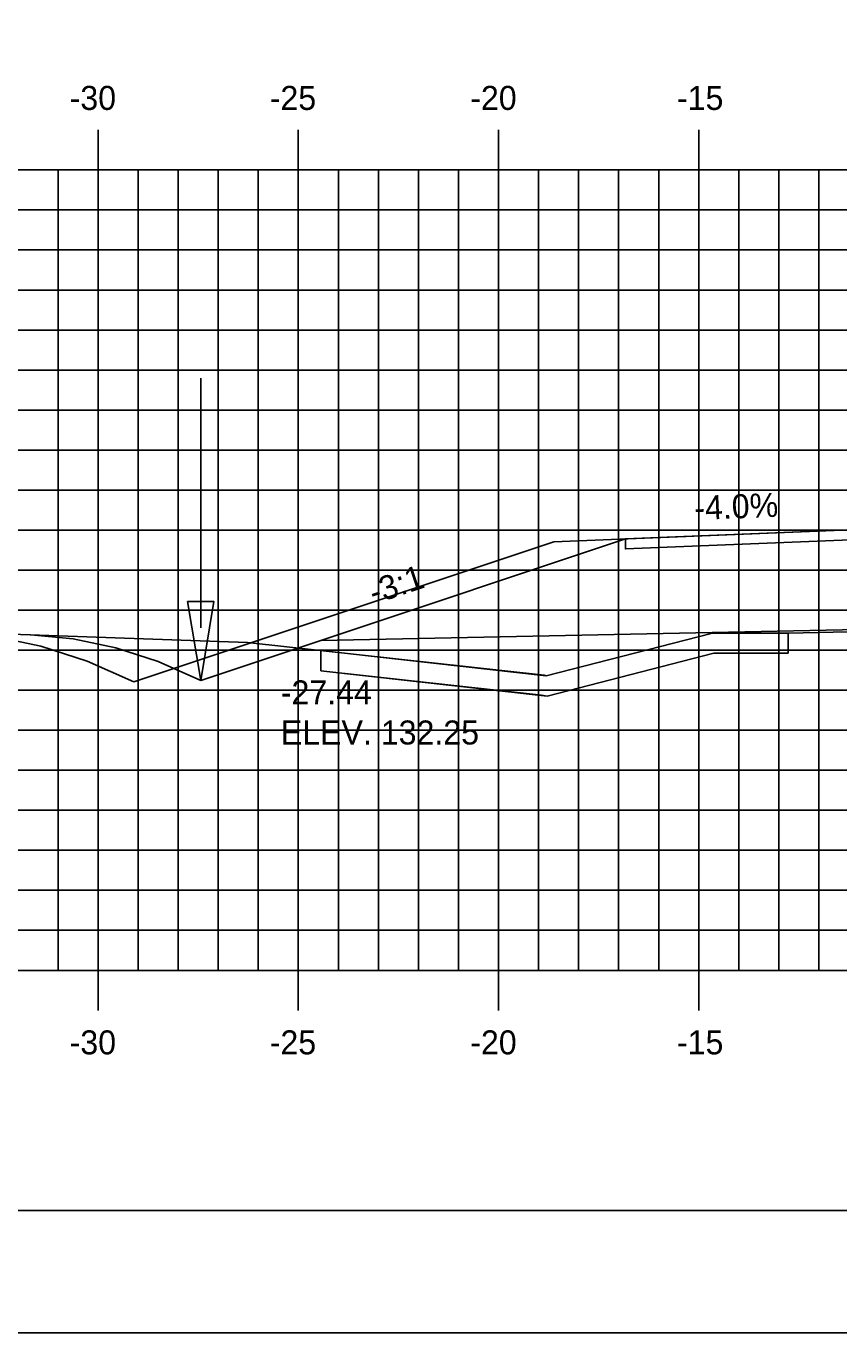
# Model space of a CAD drawing. Extents: x 1146525 to 1146695, y 608981 to 609091.
# Drawn here: x 1146575.87 to 1146596.17, y 608981.28 to 609013.93 of the extents above; entities that cross this region are included whole.
import ezdxf

# ---------------------------------------------------------------- set-up
doc = ezdxf.new("R2010")
doc.units = 0
for name, color, linetype in [('ANNOTATION', 7, 'Continuous'), ('BORDER', 7, 'Continuous'), ('D_Drainage_Ditch_Line', 7, 'Continuous'), ('D_Roadway_Edge_Shoulder', 7, 'Continuous'), ('D_Roadway_SlopeLines', 7, 'Continuous'), ('D_Roadway_SubGrade', 7, 'Continuous'), ('D_Text_Standard', 7, 'Continuous'), ('H_V ANNOTATION', 7, 'Continuous'), ('MAJOR', 7, 'Continuous'), ('MINOR', 7, 'Continuous'), ('PLOT BOUNDARY', 7, 'Continuous'), ('S_Roadway_Centerline', 7, 'Continuous'), ('SHADING', 7, 'Continuous')]:
    doc.layers.add(name, color=color, linetype=linetype)

msp = doc.modelspace()

# ---------------------------------------------------------------- linework, layer by layer
msp.add_lwpolyline([(1146573.921, 608998.789), (1146575.081, 608998.68), (1146576.241, 608998.437), (1146577.401, 608998.059), (1146578.562, 608997.547), (1146581.562, 608998.547), (1146589.055, 609001.044), (1146589.056, 609001.044), (1146596.671, 609001.349), (1146607.671, 609001.569), (1146618.671, 609001.349), (1146622.671, 609001.189), (1146630.395, 608998.614), (1146633.395, 608997.614), (1146633.841, 608997.812), (1146634.287, 608997.957), (1146634.734, 608998.049), (1146635.18, 608998.09)])
at = {"layer": 'BORDER'}
msp.add_lwpolyline([(1146532.671, 608984.335), (1146692.671, 608984.335), (1146692.671, 609089.335), (1146532.671, 609089.335)], close=True, dxfattribs=at)
at = {"layer": 'D_Drainage_Ditch_Line'}
msp.add_line((1146580.233, 608998.892), (1146580.234, 609005.136), dxfattribs=at)
msp.add_lwpolyline([(1146579.905, 608999.549), (1146580.562, 608999.549), (1146580.233, 608997.58)], close=True, dxfattribs=at)
at = {"layer": 'D_Roadway_Edge_Shoulder'}
msp.add_lwpolyline([(1146596.671, 609001.349), (1146590.841, 609001.116), (1146590.841, 609000.866), (1146596.671, 609001.099)], close=True, dxfattribs=at)
at = {"layer": 'D_Roadway_SlopeLines'}
for points in [[(1146580.233, 608997.58), (1146579.172, 608998.049), (1146578.111, 608998.395), (1146577.05, 608998.617), (1146575.989, 608998.716)], [(1146583.233, 608998.58), (1146580.233, 608997.58)]]:
    msp.add_lwpolyline(points, dxfattribs=at)
at = {"layer": 'D_Roadway_SubGrade'}
for p, q in [((1146594.907, 608998.757), (1146594.907, 608998.257)), ((1146583.233, 608998.323), (1146583.233, 608997.821))]:
    msp.add_line(p, q, dxfattribs=at)
msp.add_lwpolyline([(1146596.671, 609000.932), (1146596.671, 609001.099), (1146590.841, 609000.866), (1146590.841, 609001.116), (1146590.84, 609001.116), (1146583.233, 608998.58), (1146596.671, 608998.849)], close=True, dxfattribs=at)
msp.add_lwpolyline([(1146583.233, 608997.821), (1146588.742, 608997.212), (1146588.885, 608997.189), (1146593.05, 608998.26), (1146594.907, 608998.258)], dxfattribs=at)
at = {"layer": 'MAJOR'}
for p, q in [((1146577.671, 609011.337), (1146577.671, 609010.335)), ((1146582.671, 609011.337), (1146582.671, 609010.335)), ((1146587.671, 609011.337), (1146587.671, 609010.335)), ((1146592.671, 609011.337), (1146592.671, 609010.335)), ((1146537.671, 609010.335), (1146677.671, 609010.335)), ((1146537.671, 609010.335), (1146677.671, 609010.335)), ((1146577.671, 608990.335), (1146577.671, 609010.335)), ((1146582.671, 608990.335), (1146582.671, 609010.335)), ((1146587.671, 608990.335), (1146587.671, 609010.335)), ((1146592.671, 608990.335), (1146592.671, 609010.335)), ((1146537.671, 609005.335), (1146677.671, 609005.335)), ((1146537.671, 609000.335), (1146677.671, 609000.335)), ((1146537.671, 608995.335), (1146677.671, 608995.335)), ((1146537.671, 608990.335), (1146677.671, 608990.335)), ((1146537.671, 608990.335), (1146677.671, 608990.335)), ((1146577.671, 608989.333), (1146577.671, 608990.335)), ((1146582.671, 608989.333), (1146582.671, 608990.335)), ((1146587.671, 608989.333), (1146587.671, 608990.335)), ((1146592.671, 608989.333), (1146592.671, 608990.335))]:
    msp.add_line(p, q, dxfattribs=at)
at = {"layer": 'MINOR'}
for p, q in [((1146576.671, 608990.335), (1146576.671, 609010.335)), ((1146578.671, 608990.335), (1146578.671, 609010.335)), ((1146579.671, 608990.335), (1146579.671, 609010.335)), ((1146580.671, 608990.335), (1146580.671, 609010.335)), ((1146581.671, 608990.335), (1146581.671, 609010.335)), ((1146583.671, 608990.335), (1146583.671, 609010.335)), ((1146584.671, 608990.335), (1146584.671, 609010.335)), ((1146585.671, 608990.335), (1146585.671, 609010.335)), ((1146586.671, 608990.335), (1146586.671, 609010.335)), ((1146588.671, 608990.335), (1146588.671, 609010.335)), ((1146589.671, 608990.335), (1146589.671, 609010.335)), ((1146590.671, 608990.335), (1146590.671, 609010.335)), ((1146591.671, 608990.335), (1146591.671, 609010.335)), ((1146593.671, 608990.335), (1146593.671, 609010.335)), ((1146594.671, 608990.335), (1146594.671, 609010.335)), ((1146595.671, 608990.335), (1146595.671, 609010.335)), ((1146537.671, 609009.335), (1146677.671, 609009.335)), ((1146537.671, 609008.335), (1146677.671, 609008.335)), ((1146537.671, 609007.335), (1146677.671, 609007.335)), ((1146537.671, 609006.335), (1146677.671, 609006.335)), ((1146537.671, 609004.335), (1146677.671, 609004.335)), ((1146537.671, 609003.335), (1146677.671, 609003.335)), ((1146537.671, 609002.335), (1146677.671, 609002.335)), ((1146537.671, 609001.335), (1146677.671, 609001.335)), ((1146537.671, 608999.335), (1146677.671, 608999.335)), ((1146537.671, 608998.335), (1146677.671, 608998.335)), ((1146537.671, 608997.335), (1146677.671, 608997.335)), ((1146537.671, 608996.335), (1146677.671, 608996.335)), ((1146537.671, 608994.335), (1146677.671, 608994.335)), ((1146537.671, 608993.335), (1146677.671, 608993.335)), ((1146537.671, 608992.335), (1146677.671, 608992.335)), ((1146537.671, 608991.335), (1146677.671, 608991.335))]:
    msp.add_line(p, q, dxfattribs=at)
at = {"layer": 'PLOT BOUNDARY'}
msp.add_lwpolyline([(1146524.578, 608981.276), (1146694.578, 608981.276), (1146694.578, 609091.276), (1146524.578, 609091.276)], close=True, dxfattribs=at)
at = {"layer": 'S_Roadway_Centerline'}
msp.add_lwpolyline([(1146558.972, 608999.325), (1146561.084, 608999.24), (1146581.4, 608998.525), (1146588.809, 608997.707), (1146588.862, 608997.698), (1146592.979, 608998.756), (1146592.988, 608998.759), (1146592.993, 608998.758), (1146594.907, 608998.757), (1146601.66, 608998.911), (1146606.094, 608999.07), (1146612.762, 608998.848), (1146617.098, 608998.7), (1146618.903, 608998.533), (1146621.302, 608998.363), (1146623.626, 608997.311), (1146624.919, 608996.889), (1146629.659, 608997.697), (1146630.243, 608997.884), (1146632.151, 608997.991), (1146654.81, 608998.736), (1146655.932, 608998.78), (1146656.093, 608998.782)], dxfattribs=at)
at = {"layer": 'SHADING'}
for p, q in [((1146594.907, 608998.257), (1146594.907, 608998.757)), ((1146583.233, 608998.323), (1146583.233, 608997.821))]:
    msp.add_line(p, q, dxfattribs=at)
for points in [[(1146594.907, 608998.757), (1146592.979, 608998.756), (1146588.862, 608997.698), (1146583.233, 608998.323)], [(1146583.233, 608997.821), (1146588.885, 608997.189), (1146593.05, 608998.26), (1146594.907, 608998.257)]]:
    msp.add_lwpolyline(points, dxfattribs=at)

# ---------------------------------------------------------------- texts
at = {"layer": 'ANNOTATION'}
for s, rotation, p in [('-4.0%', 2.2906, (1146592.572, 609001.586)), ('-3:1', 18.4348, (1146584.554, 608999.474))]:
    msp.add_text(s, height=0.6, rotation=rotation, dxfattribs=at).set_placement(p)
at = {"layer": 'D_Text_Standard'}
for s, p in [('-27.44', (1146582.233, 608996.98)), ('ELEV. 132.25', (1146582.233, 608995.978))]:
    msp.add_text(s, height=0.6, dxfattribs=at).set_placement(p)
at = {"layer": 'H_V ANNOTATION'}
for s, p in [('-30', (1146576.959, 609011.835)), ('-25', (1146581.957, 609011.835)), ('-20', (1146586.965, 609011.835)), ('-15', (1146592.128, 609011.835)), ('-30', (1146576.959, 608988.235)), ('-25', (1146581.957, 608988.235)), ('-20', (1146586.965, 608988.235)), ('-15', (1146592.128, 608988.235))]:
    msp.add_text(s, height=0.6, dxfattribs=at).set_placement(p)

doc.saveas('drawing.dxf')
